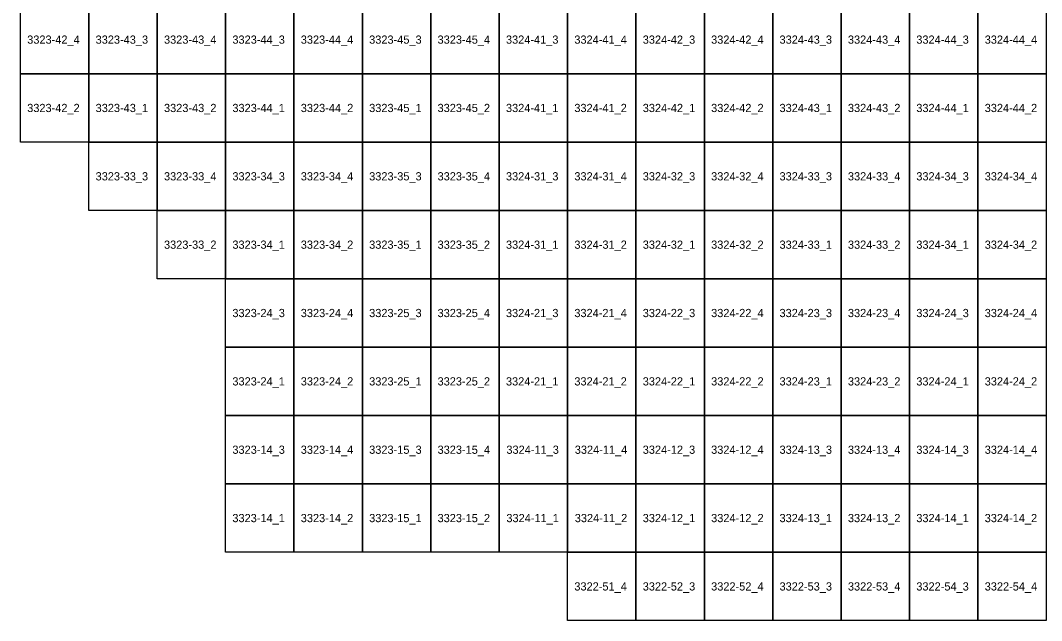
# Model space of a CAD drawing. Extents: x 312500 to 765000, y 172500 to 440000.
# Drawn here: x 557500 to 594827, y 222500 to 244452 of the extents above; entities that cross this region are included whole.
import ezdxf

# ---------------------------------------------------------------- set-up
doc = ezdxf.new("R2010")
doc.units = 0
doc.layers.add('Topo5_ramis_TKS2025', color=7, linetype='Continuous')
doc.layers.add('Topo5_ramis_TKS2025_Nr', color=7, linetype='Continuous')

msp = doc.modelspace()

# ---------------------------------------------------------------- linework, layer by layer
at = {"layer": 'Topo5_ramis_TKS2025'}
for points in [[(557500, 242500), (557500, 245000), (560000, 245000), (560000, 242500), (557500, 242500)], [(560000, 242500), (560000, 245000), (562500, 245000), (562500, 242500), (560000, 242500)], [(562500, 242500), (562500, 245000), (565000, 245000), (565000, 242500), (562500, 242500)], [(565000, 242500), (565000, 245000), (567500, 245000), (567500, 242500), (565000, 242500)], [(567500, 242500), (567500, 245000), (570000, 245000), (570000, 242500), (567500, 242500)], [(570000, 242500), (570000, 245000), (572500, 245000), (572500, 242500), (570000, 242500)], [(572500, 242500), (572500, 245000), (575000, 245000), (575000, 242500), (572500, 242500)], [(575000, 242500), (575000, 245000), (577500, 245000), (577500, 242500), (575000, 242500)], [(577500, 242500), (577500, 245000), (580000, 245000), (580000, 242500), (577500, 242500)], [(580000, 242500), (580000, 245000), (582500, 245000), (582500, 242500), (580000, 242500)], [(582500, 242500), (582500, 245000), (585000, 245000), (585000, 242500), (582500, 242500)], [(585000, 242500), (585000, 245000), (587500, 245000), (587500, 242500), (585000, 242500)], [(587500, 242500), (587500, 245000), (590000, 245000), (590000, 242500), (587500, 242500)], [(590000, 242500), (590000, 245000), (592500, 245000), (592500, 242500), (590000, 242500)], [(592500, 242500), (592500, 245000), (595000, 245000), (595000, 242500), (592500, 242500)], [(557500, 240000), (557500, 242500), (560000, 242500), (560000, 240000), (557500, 240000)], [(560000, 240000), (560000, 242500), (562500, 242500), (562500, 240000), (560000, 240000)], [(562500, 240000), (562500, 242500), (565000, 242500), (565000, 240000), (562500, 240000)], [(565000, 240000), (565000, 242500), (567500, 242500), (567500, 240000), (565000, 240000)], [(567500, 240000), (567500, 242500), (570000, 242500), (570000, 240000), (567500, 240000)], [(570000, 240000), (570000, 242500), (572500, 242500), (572500, 240000), (570000, 240000)], [(572500, 240000), (572500, 242500), (575000, 242500), (575000, 240000), (572500, 240000)], [(575000, 240000), (575000, 242500), (577500, 242500), (577500, 240000), (575000, 240000)], [(577500, 240000), (577500, 242500), (580000, 242500), (580000, 240000), (577500, 240000)], [(580000, 240000), (580000, 242500), (582500, 242500), (582500, 240000), (580000, 240000)], [(582500, 240000), (582500, 242500), (585000, 242500), (585000, 240000), (582500, 240000)], [(585000, 240000), (585000, 242500), (587500, 242500), (587500, 240000), (585000, 240000)], [(587500, 240000), (587500, 242500), (590000, 242500), (590000, 240000), (587500, 240000)], [(590000, 240000), (590000, 242500), (592500, 242500), (592500, 240000), (590000, 240000)], [(592500, 240000), (592500, 242500), (595000, 242500), (595000, 240000), (592500, 240000)], [(560000, 237500), (560000, 240000), (562500, 240000), (562500, 237500), (560000, 237500)], [(562500, 237500), (562500, 240000), (565000, 240000), (565000, 237500), (562500, 237500)], [(565000, 237500), (565000, 240000), (567500, 240000), (567500, 237500), (565000, 237500)], [(567500, 237500), (567500, 240000), (570000, 240000), (570000, 237500), (567500, 237500)], [(570000, 237500), (570000, 240000), (572500, 240000), (572500, 237500), (570000, 237500)], [(572500, 237500), (572500, 240000), (575000, 240000), (575000, 237500), (572500, 237500)], [(575000, 237500), (575000, 240000), (577500, 240000), (577500, 237500), (575000, 237500)], [(577500, 237500), (577500, 240000), (580000, 240000), (580000, 237500), (577500, 237500)], [(580000, 237500), (580000, 240000), (582500, 240000), (582500, 237500), (580000, 237500)], [(582500, 237500), (582500, 240000), (585000, 240000), (585000, 237500), (582500, 237500)], [(585000, 237500), (585000, 240000), (587500, 240000), (587500, 237500), (585000, 237500)], [(587500, 237500), (587500, 240000), (590000, 240000), (590000, 237500), (587500, 237500)], [(590000, 237500), (590000, 240000), (592500, 240000), (592500, 237500), (590000, 237500)], [(592500, 237500), (592500, 240000), (595000, 240000), (595000, 237500), (592500, 237500)], [(562500, 235000), (562500, 237500), (565000, 237500), (565000, 235000), (562500, 235000)], [(565000, 235000), (565000, 237500), (567500, 237500), (567500, 235000), (565000, 235000)], [(567500, 235000), (567500, 237500), (570000, 237500), (570000, 235000), (567500, 235000)], [(570000, 235000), (570000, 237500), (572500, 237500), (572500, 235000), (570000, 235000)], [(572500, 235000), (572500, 237500), (575000, 237500), (575000, 235000), (572500, 235000)], [(575000, 235000), (575000, 237500), (577500, 237500), (577500, 235000), (575000, 235000)], [(577500, 235000), (577500, 237500), (580000, 237500), (580000, 235000), (577500, 235000)], [(580000, 235000), (580000, 237500), (582500, 237500), (582500, 235000), (580000, 235000)], [(582500, 235000), (582500, 237500), (585000, 237500), (585000, 235000), (582500, 235000)], [(585000, 235000), (585000, 237500), (587500, 237500), (587500, 235000), (585000, 235000)], [(587500, 235000), (587500, 237500), (590000, 237500), (590000, 235000), (587500, 235000)], [(590000, 235000), (590000, 237500), (592500, 237500), (592500, 235000), (590000, 235000)], [(592500, 235000), (592500, 237500), (595000, 237500), (595000, 235000), (592500, 235000)], [(565000, 232500), (565000, 235000), (567500, 235000), (567500, 232500), (565000, 232500)], [(567500, 232500), (567500, 235000), (570000, 235000), (570000, 232500), (567500, 232500)], [(570000, 232500), (570000, 235000), (572500, 235000), (572500, 232500), (570000, 232500)], [(572500, 232500), (572500, 235000), (575000, 235000), (575000, 232500), (572500, 232500)], [(575000, 232500), (575000, 235000), (577500, 235000), (577500, 232500), (575000, 232500)], [(577500, 232500), (577500, 235000), (580000, 235000), (580000, 232500), (577500, 232500)], [(580000, 232500), (580000, 235000), (582500, 235000), (582500, 232500), (580000, 232500)], [(582500, 232500), (582500, 235000), (585000, 235000), (585000, 232500), (582500, 232500)], [(585000, 232500), (585000, 235000), (587500, 235000), (587500, 232500), (585000, 232500)], [(587500, 232500), (587500, 235000), (590000, 235000), (590000, 232500), (587500, 232500)], [(590000, 232500), (590000, 235000), (592500, 235000), (592500, 232500), (590000, 232500)], [(592500, 232500), (592500, 235000), (595000, 235000), (595000, 232500), (592500, 232500)], [(565000, 230000), (565000, 232500), (567500, 232500), (567500, 230000), (565000, 230000)], [(567500, 230000), (567500, 232500), (570000, 232500), (570000, 230000), (567500, 230000)], [(570000, 230000), (570000, 232500), (572500, 232500), (572500, 230000), (570000, 230000)], [(572500, 230000), (572500, 232500), (575000, 232500), (575000, 230000), (572500, 230000)], [(575000, 230000), (575000, 232500), (577500, 232500), (577500, 230000), (575000, 230000)], [(577500, 230000), (577500, 232500), (580000, 232500), (580000, 230000), (577500, 230000)], [(580000, 230000), (580000, 232500), (582500, 232500), (582500, 230000), (580000, 230000)], [(582500, 230000), (582500, 232500), (585000, 232500), (585000, 230000), (582500, 230000)], [(585000, 230000), (585000, 232500), (587500, 232500), (587500, 230000), (585000, 230000)], [(587500, 230000), (587500, 232500), (590000, 232500), (590000, 230000), (587500, 230000)], [(590000, 230000), (590000, 232500), (592500, 232500), (592500, 230000), (590000, 230000)], [(592500, 230000), (592500, 232500), (595000, 232500), (595000, 230000), (592500, 230000)], [(565000, 227500), (565000, 230000), (567500, 230000), (567500, 227500), (565000, 227500)], [(567500, 227500), (567500, 230000), (570000, 230000), (570000, 227500), (567500, 227500)], [(570000, 227500), (570000, 230000), (572500, 230000), (572500, 227500), (570000, 227500)], [(572500, 227500), (572500, 230000), (575000, 230000), (575000, 227500), (572500, 227500)], [(575000, 227500), (575000, 230000), (577500, 230000), (577500, 227500), (575000, 227500)], [(577500, 227500), (577500, 230000), (580000, 230000), (580000, 227500), (577500, 227500)], [(580000, 227500), (580000, 230000), (582500, 230000), (582500, 227500), (580000, 227500)], [(582500, 227500), (582500, 230000), (585000, 230000), (585000, 227500), (582500, 227500)], [(585000, 227500), (585000, 230000), (587500, 230000), (587500, 227500), (585000, 227500)], [(587500, 227500), (587500, 230000), (590000, 230000), (590000, 227500), (587500, 227500)], [(590000, 227500), (590000, 230000), (592500, 230000), (592500, 227500), (590000, 227500)], [(592500, 227500), (592500, 230000), (595000, 230000), (595000, 227500), (592500, 227500)], [(565000, 225000), (565000, 227500), (567500, 227500), (567500, 225000), (565000, 225000)], [(567500, 225000), (567500, 227500), (570000, 227500), (570000, 225000), (567500, 225000)], [(570000, 225000), (570000, 227500), (572500, 227500), (572500, 225000), (570000, 225000)], [(572500, 225000), (572500, 227500), (575000, 227500), (575000, 225000), (572500, 225000)], [(575000, 225000), (575000, 227500), (577500, 227500), (577500, 225000), (575000, 225000)], [(577500, 225000), (577500, 227500), (580000, 227500), (580000, 225000), (577500, 225000)], [(580000, 225000), (580000, 227500), (582500, 227500), (582500, 225000), (580000, 225000)], [(582500, 225000), (582500, 227500), (585000, 227500), (585000, 225000), (582500, 225000)], [(585000, 225000), (585000, 227500), (587500, 227500), (587500, 225000), (585000, 225000)], [(587500, 225000), (587500, 227500), (590000, 227500), (590000, 225000), (587500, 225000)], [(590000, 225000), (590000, 227500), (592500, 227500), (592500, 225000), (590000, 225000)], [(592500, 225000), (592500, 227500), (595000, 227500), (595000, 225000), (592500, 225000)], [(577500, 222500), (577500, 225000), (580000, 225000), (580000, 222500), (577500, 222500)], [(580000, 222500), (580000, 225000), (582500, 225000), (582500, 222500), (580000, 222500)], [(582500, 222500), (582500, 225000), (585000, 225000), (585000, 222500), (582500, 222500)], [(585000, 222500), (585000, 225000), (587500, 225000), (587500, 222500), (585000, 222500)], [(587500, 222500), (587500, 225000), (590000, 225000), (590000, 222500), (587500, 222500)], [(590000, 222500), (590000, 225000), (592500, 225000), (592500, 222500), (590000, 222500)], [(592500, 222500), (592500, 225000), (595000, 225000), (595000, 222500), (592500, 222500)]]:
    msp.add_lwpolyline(points, dxfattribs=at)

# ---------------------------------------------------------------- texts
at = {"layer": 'Topo5_ramis_TKS2025_Nr'}
for s, p in [('3323-42_4', (557748, 243600)), ('3323-43_3', (560248, 243600)), ('3323-43_4', (562748, 243600)), ('3323-44_3', (565248, 243600)), ('3323-44_4', (567748, 243600)), ('3323-45_3', (570248, 243600)), ('3323-45_4', (572748, 243600)), ('3324-41_3', (575248, 243600)), ('3324-41_4', (577748, 243600)), ('3324-42_3', (580248, 243600)), ('3324-42_4', (582748, 243600)), ('3324-43_3', (585248, 243600)), ('3324-43_4', (587748, 243600)), ('3324-44_3', (590248, 243600)), ('3324-44_4', (592748, 243600)), ('3323-42_2', (557748, 241100)), ('3323-43_1', (560248, 241100)), ('3323-43_2', (562748, 241100)), ('3323-44_1', (565248, 241100)), ('3323-44_2', (567748, 241100)), ('3323-45_1', (570248, 241100)), ('3323-45_2', (572748, 241100)), ('3324-41_1', (575248, 241100)), ('3324-41_2', (577748, 241100)), ('3324-42_1', (580248, 241100)), ('3324-42_2', (582748, 241100)), ('3324-43_1', (585248, 241100)), ('3324-43_2', (587748, 241100)), ('3324-44_1', (590248, 241100)), ('3324-44_2', (592748, 241100)), ('3323-33_3', (560248, 238600)), ('3323-33_4', (562748, 238600)), ('3323-34_3', (565248, 238600)), ('3323-34_4', (567748, 238600)), ('3323-35_3', (570248, 238600)), ('3323-35_4', (572748, 238600)), ('3324-31_3', (575248, 238600)), ('3324-31_4', (577748, 238600)), ('3324-32_3', (580248, 238600)), ('3324-32_4', (582748, 238600)), ('3324-33_3', (585248, 238600)), ('3324-33_4', (587748, 238600)), ('3324-34_3', (590248, 238600)), ('3324-34_4', (592748, 238600)), ('3323-33_2', (562748, 236100)), ('3323-34_1', (565248, 236100)), ('3323-34_2', (567748, 236100)), ('3323-35_1', (570248, 236100)), ('3323-35_2', (572748, 236100)), ('3324-31_1', (575248, 236100)), ('3324-31_2', (577748, 236100)), ('3324-32_1', (580248, 236100)), ('3324-32_2', (582748, 236100)), ('3324-33_1', (585248, 236100)), ('3324-33_2', (587748, 236100)), ('3324-34_1', (590248, 236100)), ('3324-34_2', (592748, 236100)), ('3323-24_3', (565248, 233600)), ('3323-24_4', (567748, 233600)), ('3323-25_3', (570248, 233600)), ('3323-25_4', (572748, 233600)), ('3324-21_3', (575248, 233600)), ('3324-21_4', (577748, 233600)), ('3324-22_3', (580248, 233600)), ('3324-22_4', (582748, 233600)), ('3324-23_3', (585248, 233600)), ('3324-23_4', (587748, 233600)), ('3324-24_3', (590248, 233600)), ('3324-24_4', (592748, 233600)), ('3323-24_1', (565248, 231100)), ('3323-24_2', (567748, 231100)), ('3323-25_1', (570248, 231100)), ('3323-25_2', (572748, 231100)), ('3324-21_1', (575248, 231100)), ('3324-21_2', (577748, 231100)), ('3324-22_1', (580248, 231100)), ('3324-22_2', (582748, 231100)), ('3324-23_1', (585248, 231100)), ('3324-23_2', (587748, 231100)), ('3324-24_1', (590248, 231100)), ('3324-24_2', (592748, 231100)), ('3323-14_3', (565248, 228600)), ('3323-14_4', (567748, 228600)), ('3323-15_3', (570248, 228600)), ('3323-15_4', (572748, 228600)), ('3324-11_3', (575264, 228600)), ('3324-11_4', (577764, 228600)), ('3324-12_3', (580248, 228600)), ('3324-12_4', (582748, 228600)), ('3324-13_3', (585248, 228600)), ('3324-13_4', (587748, 228600)), ('3324-14_3', (590248, 228600)), ('3324-14_4', (592748, 228600)), ('3323-14_1', (565248, 226100)), ('3323-14_2', (567748, 226100)), ('3323-15_1', (570248, 226100)), ('3323-15_2', (572748, 226100)), ('3324-11_1', (575264, 226100)), ('3324-11_2', (577764, 226100)), ('3324-12_1', (580248, 226100)), ('3324-12_2', (582748, 226100)), ('3324-13_1', (585248, 226100)), ('3324-13_2', (587748, 226100)), ('3324-14_1', (590248, 226100)), ('3324-14_2', (592748, 226100)), ('3322-51_4', (577748, 223600)), ('3322-52_3', (580248, 223600)), ('3322-52_4', (582748, 223600)), ('3322-53_3', (585248, 223600)), ('3322-53_4', (587748, 223600)), ('3322-54_3', (590248, 223600)), ('3322-54_4', (592748, 223600))]:
    msp.add_text(s, height=300, dxfattribs=at).set_placement(p)

doc.saveas('drawing.dxf')
